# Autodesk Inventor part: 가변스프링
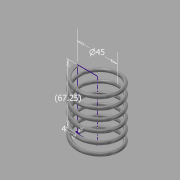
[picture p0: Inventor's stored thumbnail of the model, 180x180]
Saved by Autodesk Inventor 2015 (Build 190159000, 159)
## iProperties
Created: 2016-02
Part Number: 가변스프링
Material: 스테인레스 스틸
Document SubType Name: Modeling
Designer: Administrator
Density: 8 g/cm^3
Appearance: 반연마
Mass: 84.1995 g
Surface Area: 106.448 cm^2
Volume: 10.5249 cm^3
Author: Administrator
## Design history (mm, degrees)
sketch "스케치1"
  geometry: L1 (0, 0)-(22.5, 0); L2 (22.5, 0)-(22.5, 67.25); L3 (22.5, 67.25)-(0, 67.25); L4 (0, 67.25)-(0, 0); C1 r 2 at (22.5, 0)
  constraints: 8 end point, 2 parallel, 1 centre point, 1 coincident, 1 horizontal, 1 perpendicular
  dimensions: "d0" = 45 diameter of L2 L4; "d1" = 67.25 distance between parallel lines of L3 L1 (derived); "d2" = 4 diameter of C1
feature "코일1" sketch "스케치1" pitch "d3" = 10; turns "d5" = 6; dims "d4" = 67.25 (= d1), "d6" = 0, angle "d7" = 90 deg, angle "d8" = 90 deg, "d9" = 0, "d10" = 0
sketch "스케치2"
  geometry: L1 (-20.5, 0)-(-24.5, 0) reference; 1 further point
  constraints: 1 horizontal alignment
extrude "돌출1" cut sketch "스케치2" stored distance "d11" = 10; taper "d12" = 0 deg
node "작업 평면1"
sketch "스케치3"
  geometry: L1 (20.5, 0)-(24.5, 0) reference; 1 further point
  constraints: 1 horizontal alignment
extrude "돌출2" cut sketch "스케치3" stored distance "d13" = 10; taper "d14" = 0 deg
node "솔리드1"
node "절단 모서리 투영1"
node "절단 모서리 투영2"
